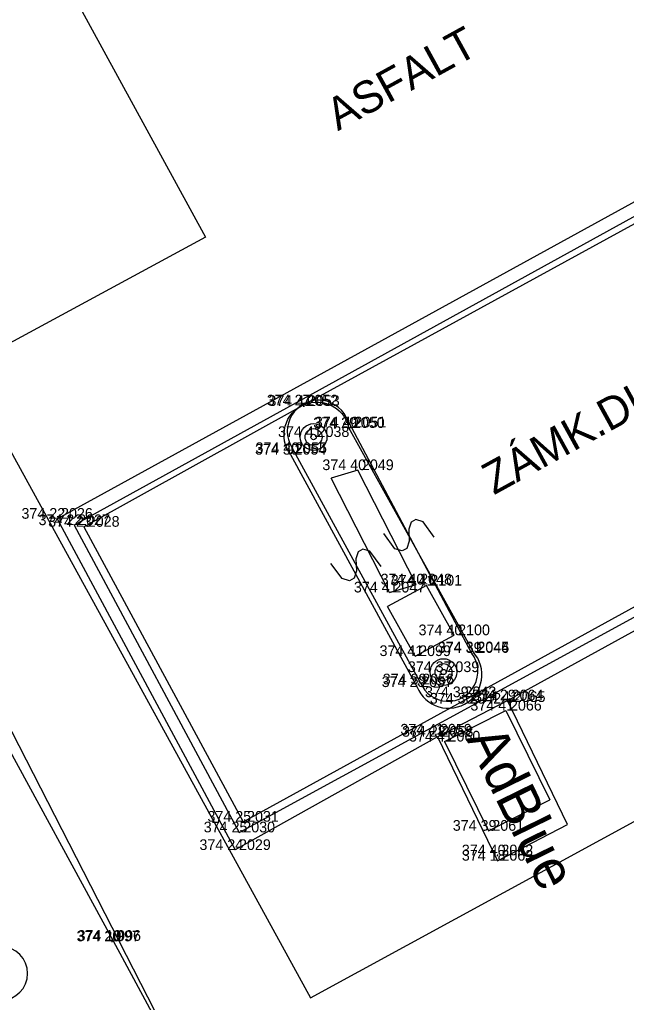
# Model space of a CAD drawing. Extents: x -601196 to -600262, y -1082523 to -1081922.
# Drawn here: x -600538.08 to -600526.73, y -1082160.12 to -1082141.73 of the extents above; entities that cross this region are included whole.
import ezdxf

# ---------------------------------------------------------------- set-up
doc = ezdxf.new("R2010")
doc.units = 0
for name, color, linetype in [('Vrstva 1', 7, 'Continuous'), ('Vrstva 10', 7, 'Continuous'), ('Vrstva 11', 7, 'Continuous'), ('Vrstva 2', 7, 'Continuous'), ('Vrstva 20', 7, 'Continuous'), ('Vrstva 22', 7, 'Continuous'), ('Vrstva 25', 7, 'Continuous'), ('Vrstva 3', 7, 'Continuous'), ('Vrstva 40', 7, 'Continuous'), ('Vrstva 41', 7, 'Continuous'), ('Vrstva 47', 7, 'Continuous')]:
    doc.layers.add(name, color=color, linetype=linetype)

msp = doc.modelspace()

# ---------------------------------------------------------------- linework, layer by layer
at = {"layer": 'Vrstva 1'}
for p, q in [((-600532.79, -1082148.95), (-600532.79, -1082148.95)), ((-600532.76, -1082148.96), (-600532.76, -1082148.96)), ((-600531.92, -1082149.37), (-600531.92, -1082149.37)), ((-600531.89, -1082149.36), (-600531.89, -1082149.36)), ((-600532.58, -1082149.54), (-600532.58, -1082149.54)), ((-600533.01, -1082149.87), (-600533.01, -1082149.87)), ((-600533, -1082149.84), (-600533, -1082149.84)), ((-600531.75, -1082150.16), (-600531.75, -1082150.16)), ((-600537.38, -1082151.07), (-600537.38, -1082151.07)), ((-600537.06, -1082151.19), (-600537.06, -1082151.19)), ((-600536.88, -1082151.22), (-600536.88, -1082151.22)), ((-600530.66, -1082152.3), (-600530.66, -1082152.3)), ((-600530.47, -1082152.32), (-600530.47, -1082152.32)), ((-600531.16, -1082152.45), (-600531.16, -1082152.45)), ((-600529.95, -1082153.25), (-600529.95, -1082153.25)), ((-600529.59, -1082153.57), (-600529.59, -1082153.57)), ((-600529.59, -1082153.57), (-600529.59, -1082153.57)), ((-600529.59, -1082153.58), (-600529.59, -1082153.58)), ((-600530.68, -1082153.64), (-600530.68, -1082153.64)), ((-600530.15, -1082153.94), (-600530.15, -1082153.94)), ((-600530.62, -1082154.17), (-600530.62, -1082154.17)), ((-600530.64, -1082154.22), (-600530.64, -1082154.22)), ((-600529.83, -1082154.41), (-600529.83, -1082154.41)), ((-600529.74, -1082154.53), (-600529.74, -1082154.53)), ((-600528.95, -1082154.47), (-600528.95, -1082154.47)), ((-600528.91, -1082154.5), (-600528.91, -1082154.5)), ((-600528.98, -1082154.66), (-600528.98, -1082154.66)), ((-600530.29, -1082155.11), (-600530.29, -1082155.11)), ((-600530.26, -1082155.15), (-600530.26, -1082155.15)), ((-600530.13, -1082155.24), (-600530.13, -1082155.24)), ((-600533.9, -1082156.74), (-600533.9, -1082156.74)), ((-600529.31, -1082156.91), (-600529.31, -1082156.91)), ((-600533.97, -1082156.94), (-600533.97, -1082156.94)), ((-600534.05, -1082157.27), (-600534.05, -1082157.27)), ((-600529.14, -1082157.37), (-600529.14, -1082157.37)), ((-600529.14, -1082157.47), (-600529.14, -1082157.47)), ((-600536.35, -1082158.98), (-600536.35, -1082158.98)), ((-600536.33, -1082158.97), (-600536.33, -1082158.97))]:
    msp.add_line(p, q, dxfattribs=at)
at = {"layer": 'Vrstva 10'}
for p, q in [((-600545.55, -1082142.03), (-600536.33, -1082158.97)), ((-600529.59, -1082153.57), (-600531.92, -1082149.37)), ((-600533.01, -1082149.87), (-600530.64, -1082154.22)), ((-600529.59, -1082153.57), (-600529.59, -1082153.57)), ((-600527.83, -1082156.79), (-600528.95, -1082154.47)), ((-600530.26, -1082155.15), (-600529.14, -1082157.47)), ((-600529.14, -1082157.47), (-600527.83, -1082156.79)), ((-600536.33, -1082158.97), (-600534.47, -1082162.42))]:
    msp.add_line(p, q, dxfattribs=at)
for points in [[(-600533.01, -1082149.87), (-600533.049, -1082149.812), (-600533.081, -1082149.75), (-600533.106, -1082149.684), (-600533.123, -1082149.616), (-600533.132, -1082149.547), (-600533.133, -1082149.477), (-600533.126, -1082149.407), (-600533.112, -1082149.339), (-600533.089, -1082149.272), (-600533.06, -1082149.209), (-600533.023, -1082149.149), (-600532.979, -1082149.094), (-600532.93, -1082149.045), (-600532.875, -1082149.001), (-600532.816, -1082148.964), (-600532.753, -1082148.933), (-600532.687, -1082148.91), (-600532.618, -1082148.895), (-600532.549, -1082148.888), (-600532.479, -1082148.889), (-600532.409, -1082148.897), (-600532.341, -1082148.914), (-600532.275, -1082148.938), (-600532.213, -1082148.969), (-600532.154, -1082149.008), (-600532.1, -1082149.053), (-600532.052, -1082149.103), (-600532.01, -1082149.159), (-600531.974, -1082149.219), (-600531.946, -1082149.283), (-600531.925, -1082149.35), (-600531.92, -1082149.37)], [(-600530.64, -1082154.22), (-600530.61, -1082154.284), (-600530.573, -1082154.345), (-600530.53, -1082154.401), (-600530.481, -1082154.451), (-600530.426, -1082154.496), (-600530.366, -1082154.534), (-600530.303, -1082154.566), (-600530.236, -1082154.59), (-600530.167, -1082154.606), (-600530.097, -1082154.615), (-600530.026, -1082154.615), (-600529.956, -1082154.608), (-600529.887, -1082154.592), (-600529.82, -1082154.569), (-600529.756, -1082154.539), (-600529.696, -1082154.501), (-600529.64, -1082154.457), (-600529.59, -1082154.407), (-600529.546, -1082154.352), (-600529.508, -1082154.292), (-600529.477, -1082154.228), (-600529.454, -1082154.162), (-600529.438, -1082154.092), (-600529.431, -1082154.022), (-600529.431, -1082153.951), (-600529.439, -1082153.881), (-600529.455, -1082153.812), (-600529.479, -1082153.745), (-600529.51, -1082153.682), (-600529.548, -1082153.622), (-600529.59, -1082153.57)]]:
    msp.add_lwpolyline(points, dxfattribs=at)
at = {"layer": 'Vrstva 11'}
for p, q in [((-600537.38, -1082151.07), (-600522.18, -1082142.72)), ((-600522.25, -1082143.02), (-600537.06, -1082151.19)), ((-600532.79, -1082148.95), (-600525.3, -1082144.85)), ((-600533.97, -1082156.94), (-600519.13, -1082148.84)), ((-600533.9, -1082156.74), (-600519.36, -1082148.75)), ((-600536.88, -1082151.22), (-600532.79, -1082148.95)), ((-600528.95, -1082154.47), (-600518.83, -1082148.91)), ((-600531.75, -1082150.16), (-600532.25, -1082150.31)), ((-600531.16, -1082152.45), (-600532.25, -1082150.31)), ((-600530.66, -1082152.3), (-600531.75, -1082150.16)), ((-600537.38, -1082151.07), (-600534.05, -1082157.27)), ((-600537.06, -1082151.19), (-600533.97, -1082156.94)), ((-600536.88, -1082151.22), (-600533.9, -1082156.74)), ((-600530.47, -1082152.32), (-600531.2, -1082152.71)), ((-600531.16, -1082152.45), (-600530.66, -1082152.3)), ((-600529.95, -1082153.25), (-600530.47, -1082152.32)), ((-600530.68, -1082153.64), (-600531.2, -1082152.71)), ((-600530.68, -1082153.64), (-600529.95, -1082153.25)), ((-600530.26, -1082155.15), (-600528.95, -1082154.47)), ((-600530.13, -1082155.24), (-600528.98, -1082154.66)), ((-600528.98, -1082154.66), (-600528.16, -1082156.33)), ((-600530.26, -1082155.15), (-600534.05, -1082157.27)), ((-600530.13, -1082155.24), (-600529.31, -1082156.91)), ((-600529.31, -1082156.91), (-600528.16, -1082156.33))]:
    msp.add_line(p, q, dxfattribs=at)
at = {"layer": 'Vrstva 20'}
for p, q in [((-600532.77, -1082148.96), (-600532.75, -1082148.96)), ((-600532.76, -1082148.945), (-600532.76, -1082148.96)), ((-600532.76, -1082148.975), (-600532.76, -1082148.96)), ((-600531.9, -1082149.36), (-600531.88, -1082149.36)), ((-600531.89, -1082149.345), (-600531.89, -1082149.36)), ((-600531.89, -1082149.375), (-600531.89, -1082149.36)), ((-600533.01, -1082149.84), (-600532.99, -1082149.84)), ((-600533, -1082149.825), (-600533, -1082149.84)), ((-600533, -1082149.855), (-600533, -1082149.84)), ((-600529.6, -1082153.58), (-600529.58, -1082153.58)), ((-600529.59, -1082153.565), (-600529.59, -1082153.58)), ((-600529.59, -1082153.595), (-600529.59, -1082153.58)), ((-600530.63, -1082154.17), (-600530.61, -1082154.17)), ((-600530.62, -1082154.155), (-600530.62, -1082154.17)), ((-600530.62, -1082154.185), (-600530.62, -1082154.17)), ((-600529.84, -1082154.41), (-600529.82, -1082154.41)), ((-600529.83, -1082154.395), (-600529.83, -1082154.41)), ((-600529.83, -1082154.425), (-600529.83, -1082154.41)), ((-600528.92, -1082154.5), (-600528.9, -1082154.5)), ((-600528.91, -1082154.485), (-600528.91, -1082154.5)), ((-600528.91, -1082154.515), (-600528.91, -1082154.5)), ((-600530.29, -1082155.095), (-600530.29, -1082155.11)), ((-600530.3, -1082155.11), (-600530.28, -1082155.11)), ((-600530.29, -1082155.125), (-600530.29, -1082155.11)), ((-600529.15, -1082157.37), (-600529.13, -1082157.37)), ((-600529.14, -1082157.355), (-600529.14, -1082157.37)), ((-600529.14, -1082157.385), (-600529.14, -1082157.37)), ((-600536.36, -1082158.98), (-600536.34, -1082158.98)), ((-600536.35, -1082158.965), (-600536.35, -1082158.98)), ((-600536.35, -1082158.995), (-600536.35, -1082158.98))]:
    msp.add_line(p, q, dxfattribs=at)
at = {"layer": 'Vrstva 22'}
msp.add_arc((-600538.43, -1082159.58), 0.5, 270, 90, dxfattribs=at)
at = {"layer": 'Vrstva 25'}
for centre, radius in [((-600532.58, -1082149.54), 0.25), ((-600532.58, -1082149.54), 0.158), ((-600532.58, -1082149.54), 0.05), ((-600530.15, -1082153.94), 0.25), ((-600530.15, -1082153.94), 0.158), ((-600530.15, -1082153.94), 0.05)]:
    msp.add_circle(centre, radius, dxfattribs=at)
at = {"layer": 'Vrstva 47'}
for p, q in [((-600537.38, -1082140.72), (-600534.6, -1082145.8)), ((-600534.6, -1082145.8), (-600539.11, -1082148.24)), ((-600541.74, -1082148.21), (-600534.49, -1082162.35)), ((-600539.11, -1082148.24), (-600532.64, -1082160.04)), ((-600529.62, -1082153.59), (-600531.97, -1082149.17)), ((-600530.58, -1082154.14), (-600532.99, -1082149.73)), ((-600532.64, -1082160.04), (-600516.16, -1082151.05)), ((-600530.756, -1082151.133), (-600530.797, -1082151.268)), ((-600530.668, -1082151.086), (-600530.756, -1082151.133)), ((-600530.532, -1082151.127), (-600530.668, -1082151.086)), ((-600530.324, -1082151.412), (-600530.532, -1082151.127)), ((-600531.057, -1082151.632), (-600531.265, -1082151.347)), ((-600530.797, -1082151.268), (-600530.792, -1082151.491)), ((-600530.792, -1082151.491), (-600530.833, -1082151.627)), ((-600531.749, -1082151.687), (-600531.789, -1082151.823)), ((-600531.661, -1082151.639), (-600531.749, -1082151.687)), ((-600531.525, -1082151.679), (-600531.661, -1082151.639)), ((-600531.314, -1082151.962), (-600531.525, -1082151.679)), ((-600530.921, -1082151.673), (-600531.057, -1082151.632)), ((-600530.833, -1082151.627), (-600530.921, -1082151.673)), ((-600532.044, -1082152.19), (-600532.255, -1082151.907)), ((-600531.789, -1082151.823), (-600531.78, -1082152.046)), ((-600531.78, -1082152.046), (-600531.82, -1082152.182)), ((-600531.908, -1082152.23), (-600532.044, -1082152.19)), ((-600531.82, -1082152.182), (-600531.908, -1082152.23))]:
    msp.add_line(p, q, dxfattribs=at)
for centre, radius, start, end in [((-600532.49, -1082149.432), 0.582, 26.7839, 210.7514), ((-600530.065, -1082153.927), 0.558, 202.5046, 37.1136)]:
    msp.add_arc(centre, radius, start, end, dxfattribs=at)

# ---------------------------------------------------------------- texts
at = {"layer": 'Vrstva 2'}
for s, p in [(' 2052', (-600532.79, -1082148.95)), (' 2053', (-600532.76, -1082148.96)), (' 2050', (-600531.92, -1082149.37)), (' 2051', (-600531.89, -1082149.36)), (' 2038', (-600532.58, -1082149.54)), (' 2054', (-600533.01, -1082149.87)), (' 2055', (-600533, -1082149.84)), (' 2049', (-600531.75, -1082150.16)), (' 2026', (-600537.38, -1082151.07)), (' 2027', (-600537.06, -1082151.19)), (' 2028', (-600536.88, -1082151.22)), (' 2048', (-600530.66, -1082152.3)), (' 2101', (-600530.47, -1082152.32)), (' 2047', (-600531.16, -1082152.45)), (' 2100', (-600529.95, -1082153.25)), (' 2099', (-600530.68, -1082153.64)), (' 2044', (-600529.59, -1082153.57)), (' 2045', (-600529.59, -1082153.57)), (' 2046', (-600529.59, -1082153.58)), (' 2039', (-600530.15, -1082153.94)), (' 2056', (-600530.62, -1082154.17)), (' 2057', (-600530.64, -1082154.22)), (' 2043', (-600529.83, -1082154.41)), (' 2042', (-600529.74, -1082154.53)), (' 2064', (-600528.95, -1082154.47)), (' 2065', (-600528.91, -1082154.5)), (' 2066', (-600528.98, -1082154.66)), (' 2059', (-600530.29, -1082155.11)), (' 2058', (-600530.26, -1082155.15)), (' 2060', (-600530.13, -1082155.24)), (' 2031', (-600533.9, -1082156.74)), (' 2030', (-600533.97, -1082156.94)), (' 2061', (-600529.31, -1082156.91)), (' 2029', (-600534.05, -1082157.27)), (' 2062', (-600529.14, -1082157.37)), (' 2063', (-600529.14, -1082157.47)), (' 996', (-600536.33, -1082158.97)), (' 997', (-600536.35, -1082158.98))]:
    msp.add_text(s, height=0.2, dxfattribs=at).set_placement(p)
at = {"layer": 'Vrstva 3'}
for s, p in [('374 27 ', (-600533.456, -1082148.95)), ('374 41 ', (-600533.426, -1082148.96)), ('374 29 ', (-600532.586, -1082149.37)), ('374 40 ', (-600532.556, -1082149.36)), ('374 41 ', (-600533.246, -1082149.54)), ('374 30 ', (-600533.676, -1082149.87)), ('374 40 ', (-600533.666, -1082149.84)), ('374 40 ', (-600532.416, -1082150.16)), ('374 22 ', (-600538.046, -1082151.07)), ('374 22 ', (-600537.726, -1082151.19)), ('374 23 ', (-600537.546, -1082151.22)), ('374 40 ', (-600531.326, -1082152.3)), ('374 41 ', (-600531.136, -1082152.32)), ('374 41 ', (-600531.826, -1082152.45)), ('374 40 ', (-600530.616, -1082153.25)), ('374 41 ', (-600531.346, -1082153.64)), ('374 31 ', (-600530.256, -1082153.57)), ('374 31 ', (-600530.256, -1082153.57)), ('374 39 ', (-600530.256, -1082153.58)), ('374 37 ', (-600530.816, -1082153.94)), ('374 39 ', (-600531.286, -1082154.17)), ('374 29 ', (-600531.306, -1082154.22)), ('374 39 ', (-600530.496, -1082154.41)), ('374 30 ', (-600530.406, -1082154.53)), ('374 29 ', (-600529.616, -1082154.47)), ('374 41 ', (-600529.576, -1082154.5)), ('374 41 ', (-600529.646, -1082154.66)), ('374 41 ', (-600530.956, -1082155.11)), ('374 28 ', (-600530.926, -1082155.15)), ('374 41 ', (-600530.796, -1082155.24)), ('374 25 ', (-600534.566, -1082156.74)), ('374 25 ', (-600534.636, -1082156.94)), ('374 39 ', (-600529.976, -1082156.91)), ('374 24 ', (-600534.716, -1082157.27)), ('374 40 ', (-600529.806, -1082157.37)), ('374 18 ', (-600529.806, -1082157.47)), ('374 10 ', (-600536.996, -1082158.97)), ('374 20 ', (-600537.016, -1082158.98))]:
    msp.add_text(s, height=0.2, dxfattribs=at).set_placement(p)
at = {"layer": 'Vrstva 40'}
for s, rotation, p in [('ASFALT', 28.7818, (-600532.126, -1082143.818)), ('ZÁMK.DL.', 28.7896, (-600529.208, -1082150.632))]:
    msp.add_text(s, height=0.6, rotation=rotation, dxfattribs=at).set_placement(p)
at = {"layer": 'Vrstva 41'}
msp.add_text('AdBlue', height=0.75, rotation=296.1519, dxfattribs=at).set_placement((-600529.734, -1082155.185))

doc.saveas('drawing.dxf')
